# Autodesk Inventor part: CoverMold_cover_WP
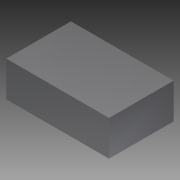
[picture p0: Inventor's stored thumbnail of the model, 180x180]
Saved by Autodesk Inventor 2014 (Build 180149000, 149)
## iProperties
Created: 2009-12
Part Number: CoverMold_cover_WP
Document SubType Name: Modeling
Designer: gaom
Density: 1 g/cm^3
Material: Generic
Appearance: Light Gray
Xmin: -175.000 mm
Ymin: -110.000 mm
Zmin: -60.000 mm
Xmax: 175.000 mm
Ymax: 110.000 mm
Zmax: 60.000 mm
d0: -60.000 mm
d1: 175.000 mm
d2: 175.000 mm
d3: 110.000 mm
d4: 110.000 mm
d5: 120.000 mm
d6: 0.00 deg
Author: gaom
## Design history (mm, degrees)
sketch "Sketch1"
  geometry: L1 (-175, 110)-(175, 110); L2 (175, 110)-(175, -110); L3 (175, -110)-(-175, -110); L4 (-175, -110)-(-175, 110); 1 further point
  constraints: 8 end point, 2 parallel, 1 horizontal, 1 perpendicular, 1 other
  dimensions: "d1" = 175 distance from line of L4 point (0, 0) (= -Xmin); "d2" = 175 distance from line of L2 point (0, 0) (= Xmax); "d3" = 110 distance from line of L3 point (0, 0) (= -Ymin); "d4" = 110 distance from line of L1 point (0, 0) (= Ymax)
extrude "Extrusion1" join sketch "Sketch1" distance "d5" = 120 (= Zmax - Zmin); taper "d6" = 0 deg
body "Solid1"
other parameters: "Xmin" = -175 [user parameter; used in 1 equation term], "Ymin" = -110 [user parameter; used in 1 equation term], "Zmin" = -60 [user parameter; used in 1 equation term], "Xmax" = 175 [user parameter; used in 1 equation term], "Ymax" = 110 [user parameter; used in 1 equation term], "Zmax" = 60 [user parameter; used in 1 equation term], "d0" = -60
